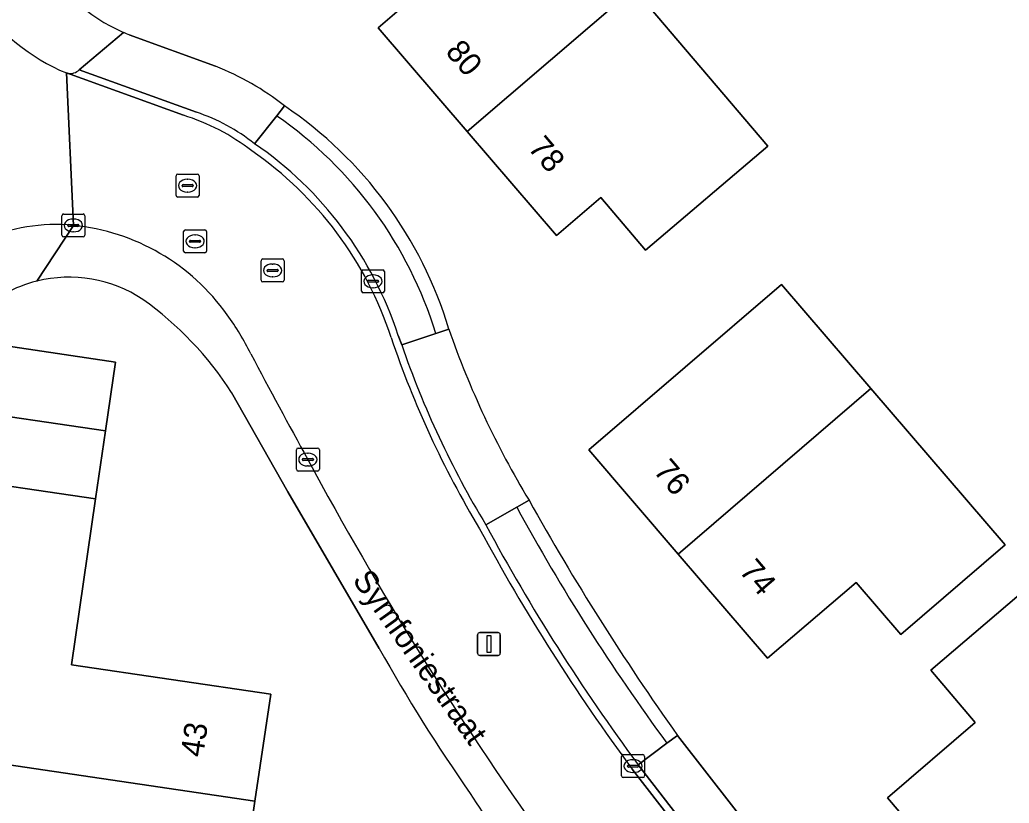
# Model space of a CAD drawing. Extents: x 164148 to 165261, y 382513 to 383432.
# Drawn here: x 164542.81 to 164585.98, y 383274.98 to 383309.16 of the extents above; entities that cross this region are included whole.
import ezdxf

# ---------------------------------------------------------------- set-up
doc = ezdxf.new("R2010")
doc.units = 0
for name, color, linetype in [('IMGEO_Erf', 7, 'Continuous'), ('IMGEO_Kolk', 7, 'Continuous'), ('IMGEO_Lichtmast', 7, 'Continuous'), ('IMGEO_Openbare_ruimte_label', 7, 'Continuous'), ('IMGEO_Pand', 7, 'Continuous'), ('IMGEO_Pand_nummerreeks', 7, 'Continuous'), ('IMGEO_Parkeervlak_open', 7, 'Continuous'), ('IMGEO_Rijbaan_lokaal_open', 7, 'Continuous'), ('IMGEO_Rioolput', 7, 'Continuous'), ('IMGEO_Voetpad_open', 7, 'Continuous')]:
    doc.layers.add(name, color=color, linetype=linetype)

msp = doc.modelspace()

# ---------------------------------------------------------------- linework, layer by layer
at = {"layer": 'IMGEO_Erf'}
for points in [[(164566.222, 383299.749), (164562.332, 383304.282), (164558.441, 383308.814), (164560.383, 383310.481), (164558.414, 383312.774), (164562.969, 383316.671), (164568.685, 383310.059), (164569.447, 383310.707), (164569.603, 383310.523), (164575.452, 383303.652), (164570.113, 383299.108), (164568.162, 383301.401)], [(164575.428, 383281.306), (164571.531, 383285.848), (164567.633, 383290.391), (164576.048, 383297.611), (164579.945, 383293.069), (164585.796, 383286.25), (164581.243, 383282.343), (164579.295, 383284.613)], [(164588.439, 383266.118), (164586.724, 383268.118), (164586.214, 383267.684), (164584.449, 383269.761), (164584.944, 383270.195), (164584.546, 383270.661), (164580.662, 383275.211), (164584.498, 383278.504), (164582.553, 383280.79), (164588.787, 383286.094), (164594.61, 383279.268), (164594.769, 383279.082), (164593.111, 383277.661), (164598.792, 383271.032), (164593.881, 383266.823), (164591.925, 383269.105)]]:
    msp.add_lwpolyline(points, close=True, dxfattribs=at)
for points in [[(164547.58, 383308.512), (164551.344, 383307.132)], [(164540.939, 383296.326), (164540.567, 383295.814), (164540.337, 383295.423), (164540.249, 383295.225), (164546.982, 383294.222), (164546.544, 383291.22), (164546.111, 383288.252), (164545.056, 383281.021), (164553.756, 383279.732), (164553.067, 383275.067), (164552.375, 383270.375), (164543.647, 383271.663), (164543.047, 383267.603), (164542.443, 383263.513), (164550.997, 383262.244), (164559.534, 383260.978), (164560.177, 383265.291), (164566.914, 383264.296), (164565.584, 383255.322), (164564.251, 383246.318), (164583.934, 383243.607)], [(164558.482, 383281.733), (164554.501, 383288.56), (164552.049, 383292.901)], [(164571.503, 383277.936), (164576.415, 383271.617), (164580.653, 383266.29), (164582.585, 383263.961), (164583.944, 383262.272), (164585.284, 383260.567)]]:
    msp.add_lwpolyline(points, dxfattribs=at)
for centre, radius, start, end in [((164550.138, 383315.173), 7.135, 166.9987, 246.8254), ((164550.095, 383315.035), 6.991, 246.698, 248.9111), ((164547.2, 383296.429), 11.477, 51.4118, 68.8368), ((164544.282, 383290.474), 18.01, 16.7439, 55.9762), ((164544.956, 383292.103), 5.829, 103.9701, 133.5672), ((164544.954, 383292.112), 5.819, 56.42, 103.9687), ((164539.532, 383284.826), 14.896, 32.8263, 54.5462), ((164598.416, 383308.4), 39.025, 199.0502, 211.1685), ((164661.715, 383342.047), 110.672, 209.1126, 215.40047), ((164627.145, 383320.437), 78.819, 209.40896, 214.84708), ((164640.067, 383326.157), 92.732, 213.18571, 215.54367)]:
    msp.add_arc(centre, radius, start, end, dxfattribs=at)
at = {"layer": 'IMGEO_Kolk'}
for p, q in [((164544.641, 383299.761), (164544.641, 383300.613)), ((164544.716, 383300.687), (164545.568, 383300.687)), ((164545.642, 383300.613), (164545.642, 383299.761)), ((164544.9, 383300.181), (164544.9, 383300.193)), ((164545.338, 383300.144), (164544.94, 383300.144)), ((164544.943, 383300.23), (164545.341, 383300.23)), ((164545.129, 383300.467), (164545.154, 383300.467)), ((164545.384, 383300.193), (164545.384, 383300.181)), ((164545.152, 383299.907), (164545.127, 383299.907)), ((164545.568, 383299.687), (164544.716, 383299.687)), ((164553.335, 383297.798), (164553.335, 383298.65)), ((164553.41, 383298.724), (164554.262, 383298.724)), ((164553.823, 383298.504), (164553.848, 383298.504)), ((164554.336, 383298.65), (164554.336, 383297.798)), ((164553.594, 383298.218), (164553.594, 383298.23)), ((164554.032, 383298.181), (164553.634, 383298.181)), ((164553.637, 383298.267), (164554.035, 383298.267)), ((164554.078, 383298.23), (164554.078, 383298.218)), ((164557.717, 383297.324), (164557.717, 383298.176)), ((164557.792, 383298.25), (164558.644, 383298.25)), ((164558.205, 383298.03), (164558.23, 383298.03)), ((164558.718, 383298.176), (164558.718, 383297.324)), ((164554.262, 383297.724), (164553.41, 383297.724)), ((164553.846, 383297.944), (164553.821, 383297.944)), ((164557.976, 383297.744), (164557.976, 383297.756)), ((164558.414, 383297.707), (164558.016, 383297.707)), ((164558.019, 383297.793), (164558.417, 383297.793)), ((164558.46, 383297.756), (164558.46, 383297.744)), ((164558.644, 383297.25), (164557.792, 383297.25)), ((164558.228, 383297.47), (164558.203, 383297.47)), ((164554.875, 383289.547), (164554.875, 383290.399)), ((164554.95, 383290.473), (164555.802, 383290.473)), ((164555.363, 383290.253), (164555.388, 383290.253)), ((164555.876, 383290.399), (164555.876, 383289.547)), ((164555.134, 383289.967), (164555.134, 383289.979)), ((164555.572, 383289.93), (164555.174, 383289.93)), ((164555.177, 383290.016), (164555.575, 383290.016)), ((164555.618, 383289.979), (164555.618, 383289.967)), ((164555.802, 383289.473), (164554.95, 383289.473)), ((164555.386, 383289.693), (164555.361, 383289.693)), ((164569.063, 383276.171), (164569.063, 383277.023)), ((164569.138, 383277.097), (164569.99, 383277.097)), ((164569.551, 383276.877), (164569.576, 383276.877)), ((164570.064, 383277.023), (164570.064, 383276.171)), ((164569.322, 383276.591), (164569.322, 383276.603)), ((164569.76, 383276.554), (164569.362, 383276.554)), ((164569.365, 383276.64), (164569.763, 383276.64)), ((164569.806, 383276.603), (164569.806, 383276.591)), ((164569.99, 383276.097), (164569.138, 383276.097)), ((164569.574, 383276.317), (164569.549, 383276.317))]:
    msp.add_line(p, q, dxfattribs=at)
for points in [[(164544.641, 383299.761), (164544.641, 383300.613)], [(164544.716, 383300.687), (164545.568, 383300.687)], [(164545.642, 383300.613), (164545.642, 383299.761)], [(164545.568, 383299.687), (164544.716, 383299.687)], [(164553.335, 383297.798), (164553.335, 383298.65)], [(164553.41, 383298.724), (164554.262, 383298.724)], [(164554.336, 383298.65), (164554.336, 383297.798)], [(164557.717, 383297.324), (164557.717, 383298.176)], [(164557.792, 383298.25), (164558.644, 383298.25)], [(164558.718, 383298.176), (164558.718, 383297.324)], [(164554.262, 383297.724), (164553.41, 383297.724)], [(164558.644, 383297.25), (164557.792, 383297.25)], [(164554.875, 383289.547), (164554.875, 383290.399)], [(164554.95, 383290.473), (164555.802, 383290.473)], [(164555.876, 383290.399), (164555.876, 383289.547)], [(164555.802, 383289.473), (164554.95, 383289.473)], [(164569.063, 383276.171), (164569.063, 383277.023)], [(164569.138, 383277.097), (164569.99, 383277.097)], [(164570.064, 383277.023), (164570.064, 383276.171)], [(164569.99, 383276.097), (164569.138, 383276.097)]]:
    msp.add_lwpolyline(points, dxfattribs=at)
for centre, radius, start, end in [((164544.718, 383300.611), 0.0765, 91.552, 178.448), ((164544.718, 383300.611), 0.0765, 91.552, 178.448), ((164545.566, 383300.611), 0.0765, 1.552, 88.448), ((164545.566, 383300.611), 0.0765, 1.552, 88.448), ((164544.94, 383300.19), 0.0403, 85.8775, 175.7526), ((164544.937, 383300.18), 0.0366, 178.938, 274.7102), ((164545.341, 383300.187), 0.043, 264.8664, 352.4533), ((164545.345, 383300.192), 0.0386, 1.7309, 96.639), ((164544.718, 383299.763), 0.0765, 181.552, 268.448), ((164544.718, 383299.763), 0.0765, 181.552, 268.448), ((164545.566, 383299.763), 0.0765, 271.552, 358.448), ((164545.566, 383299.763), 0.0765, 271.552, 358.448), ((164553.412, 383298.648), 0.0765, 91.552, 178.448), ((164553.412, 383298.648), 0.0765, 91.552, 178.448), ((164554.26, 383298.648), 0.0765, 1.552, 88.448), ((164554.26, 383298.648), 0.0765, 1.552, 88.448), ((164553.634, 383298.227), 0.0403, 85.8775, 175.7526), ((164553.631, 383298.217), 0.0366, 178.938, 274.7102), ((164554.035, 383298.224), 0.043, 264.8664, 352.4533), ((164554.039, 383298.229), 0.0386, 1.7309, 96.639), ((164557.794, 383298.174), 0.0765, 91.552, 178.448), ((164557.794, 383298.174), 0.0765, 91.552, 178.448), ((164558.642, 383298.174), 0.0765, 1.552, 88.448), ((164558.642, 383298.174), 0.0765, 1.552, 88.448), ((164553.412, 383297.8), 0.0765, 181.552, 268.448), ((164553.412, 383297.8), 0.0765, 181.552, 268.448), ((164554.26, 383297.8), 0.0765, 271.552, 358.448), ((164554.26, 383297.8), 0.0765, 271.552, 358.448), ((164558.016, 383297.753), 0.0403, 85.8775, 175.7526), ((164558.013, 383297.743), 0.0366, 178.938, 274.7102), ((164558.417, 383297.75), 0.043, 264.8664, 352.4533), ((164558.421, 383297.755), 0.0386, 1.7309, 96.639), ((164557.794, 383297.326), 0.0765, 181.552, 268.448), ((164557.794, 383297.326), 0.0765, 181.552, 268.448), ((164558.642, 383297.326), 0.0765, 271.552, 358.448), ((164558.642, 383297.326), 0.0765, 271.552, 358.448), ((164554.952, 383290.397), 0.0765, 91.552, 178.448), ((164554.952, 383290.397), 0.0765, 91.552, 178.448), ((164555.8, 383290.397), 0.0765, 1.552, 88.448), ((164555.8, 383290.397), 0.0765, 1.552, 88.448), ((164555.174, 383289.976), 0.0403, 85.8775, 175.7526), ((164555.171, 383289.966), 0.0366, 178.938, 274.7102), ((164555.575, 383289.973), 0.043, 264.8664, 352.4533), ((164555.579, 383289.978), 0.0386, 1.7309, 96.639), ((164554.952, 383289.549), 0.0765, 181.552, 268.448), ((164554.952, 383289.549), 0.0765, 181.552, 268.448), ((164555.8, 383289.549), 0.0765, 271.552, 358.448), ((164555.8, 383289.549), 0.0765, 271.552, 358.448), ((164569.14, 383277.021), 0.0765, 91.552, 178.448), ((164569.14, 383277.021), 0.0765, 91.552, 178.448), ((164569.988, 383277.021), 0.0765, 1.552, 88.448), ((164569.988, 383277.021), 0.0765, 1.552, 88.448), ((164569.362, 383276.6), 0.0403, 85.8775, 175.7526), ((164569.359, 383276.59), 0.0366, 178.938, 274.7102), ((164569.763, 383276.597), 0.043, 264.8664, 352.4533), ((164569.767, 383276.602), 0.0386, 1.7309, 96.639), ((164569.14, 383276.173), 0.0765, 181.552, 268.448), ((164569.14, 383276.173), 0.0765, 181.552, 268.448), ((164569.988, 383276.173), 0.0765, 271.552, 358.448), ((164569.988, 383276.173), 0.0765, 271.552, 358.448)]:
    msp.add_arc(centre, radius, start, end, dxfattribs=at)
for centre, major_axis, ratio, start_param, end_param in [((164545.128, 383300.187), (-0.387, 0.002), 0.722429, 4.712389, 7.853982), ((164545.153, 383300.187), (-0.39, 0.002), 0.717154, 1.570796, 4.712389), ((164553.822, 383298.224), (-0.387, 0.002), 0.722429, 4.712389, 7.853982), ((164553.847, 383298.224), (-0.39, 0.002), 0.717154, 1.570796, 4.712389), ((164558.204, 383297.75), (-0.387, 0.002), 0.722429, 4.712389, 7.853982), ((164558.229, 383297.75), (-0.39, 0.002), 0.717154, 1.570796, 4.712389), ((164555.362, 383289.973), (-0.387, 0.002), 0.722429, 4.712389, 7.853982), ((164555.387, 383289.973), (-0.39, 0.002), 0.717154, 1.570796, 4.712389), ((164569.55, 383276.597), (-0.387, 0.002), 0.722429, 4.712389, 7.853982), ((164569.575, 383276.597), (-0.39, 0.002), 0.717154, 1.570796, 4.712389)]:
    msp.add_ellipse(centre, major_axis=major_axis, ratio=ratio, start_param=start_param, end_param=end_param, dxfattribs=at)
at = {"layer": 'IMGEO_Lichtmast'}
for p, q in [((164562.783, 383281.525), (164562.783, 383282.325)), ((164562.783, 383282.325), (164562.783, 383281.525)), ((164562.883, 383282.425), (164563.673, 383282.425)), ((164563.673, 383282.425), (164562.883, 383282.425)), ((164563.773, 383282.325), (164563.773, 383281.525)), ((164563.773, 383281.525), (164563.773, 383282.325)), ((164563.673, 383281.425), (164562.883, 383281.425)), ((164562.883, 383281.425), (164563.673, 383281.425))]:
    msp.add_line(p, q, dxfattribs=at)
msp.add_lwpolyline([(164563.203, 383282.3), (164563.353, 383282.3), (164563.353, 383281.55), (164563.203, 383281.55), (164563.203, 383282.3)], dxfattribs=at)
for centre, start, end in [((164562.883, 383282.325), 90, 180), ((164562.883, 383282.325), 90, 180), ((164563.673, 383282.325), 0, 90), ((164563.673, 383282.325), 360, 90), ((164562.883, 383281.525), 180, 270), ((164562.883, 383281.525), 180, 270), ((164563.673, 383281.525), 270, 0), ((164563.673, 383281.525), 270, 0)]:
    msp.add_arc(centre, 0.1, start, end, dxfattribs=at)
at = {"layer": 'IMGEO_Pand'}
for points in [[(164569.603, 383310.523), (164569.447, 383310.707), (164568.685, 383310.059), (164562.969, 383316.671), (164558.414, 383312.774), (164560.383, 383310.481), (164558.441, 383308.814), (164562.332, 383304.282)], [(164569.603, 383310.523), (164562.332, 383304.282), (164566.222, 383299.749), (164568.162, 383301.401), (164570.113, 383299.108), (164575.452, 383303.652)], [(164579.945, 383293.069), (164576.048, 383297.611), (164567.633, 383290.391), (164571.531, 383285.848)], [(164539.803, 383292.218), (164546.544, 383291.22), (164546.982, 383294.222), (164540.249, 383295.225)], [(164579.945, 383293.069), (164571.531, 383285.848), (164575.428, 383281.306), (164579.295, 383284.613), (164581.243, 383282.343), (164585.796, 383286.25)], [(164539.362, 383289.25), (164546.111, 383288.252), (164546.544, 383291.22), (164539.803, 383292.218)], [(164537.597, 383277.356), (164553.067, 383275.067), (164553.756, 383279.732), (164545.056, 383281.021), (164546.111, 383288.252), (164539.362, 383289.25)], [(164594.61, 383279.268), (164588.787, 383286.094), (164582.553, 383280.79), (164584.498, 383278.504), (164580.662, 383275.211), (164584.546, 383270.661)], [(164543.047, 383267.603), (164543.647, 383271.663), (164552.375, 383270.375), (164553.067, 383275.067), (164537.597, 383277.356), (164536.299, 383268.602)]]:
    msp.add_lwpolyline(points, close=True, dxfattribs=at)
at = {"layer": 'IMGEO_Parkeervlak_open'}
for points in [[(164554.014, 383304.967), (164553.048, 383303.754)], [(164559.317, 383295.392), (164559.471, 383294.976), (164560.956, 383295.471)], [(164564.487, 383287.893), (164563.142, 383287.12)], [(164569.788, 383276.659), (164571.04, 383277.591)]]:
    msp.add_lwpolyline(points, dxfattribs=at)
for centre, radius, start, end in [((164543.848, 383290.25), 17.887, 16.9716, 55.3654), ((164543.862, 383290.337), 16.26, 18.1136, 55.6043), ((164645.11, 383331.941), 91.871, 208.64996, 216.27011), ((164639.103, 383328.038), 86.281, 208.30968, 216.5469)]:
    msp.add_arc(centre, radius, start, end, dxfattribs=at)
at = {"layer": 'IMGEO_Rijbaan_lokaal_open'}
for points in [[(164544.837, 383306.841), (164549.942, 383304.996)], [(164545.142, 383300.187), (164544.837, 383306.841)], [(164549.942, 383304.996), (164544.837, 383306.841), (164545.142, 383300.187)], [(164550.516, 383305.129), (164545.397, 383306.979), (164545.349, 383306.939)], [(164559.471, 383294.976), (164559.317, 383295.392)], [(164569.53, 383276.467), (164574.452, 383270.101)], [(164574.452, 383270.101), (164569.53, 383276.467)], [(164574.707, 383270.298), (164569.788, 383276.659)]]:
    msp.add_lwpolyline(points, dxfattribs=at)
for centre, radius, start, end in [((164548.388, 383315.25), 9.129, 215.2111, 247.1054), ((164545.003, 383307.359), 0.544, 252.2305, 309.441), ((164547.197, 383296.08), 9.329, 52.0782, 72.8909), ((164547.197, 383296.08), 9.329, 52.0782, 72.8909), ((164547.938, 383297.362), 8.183, 51.3566, 71.6351), ((164543.862, 383290.337), 16.26, 18.1136, 55.6043), ((164543.897, 383290.355), 15.9, 18.0902, 55.3768), ((164543.897, 383290.355), 15.9, 18.0902, 55.3768), ((164544.352, 383292.464), 7.763, 84.1568, 143.902), ((164544.251, 383290.931), 9.298, 35.1831, 84.5028), ((164542.3, 383289.297), 11.837, 26.5256, 36.2085), ((164599.247, 383308.839), 42.455, 198.6077, 211.0297), ((164599.247, 383308.839), 42.455, 198.6077, 211.0297), ((164598.458, 383308.408), 41.236, 199.0106, 211.0815), ((164748.715, 383397.166), 221.066, 207.648, 209.00538), ((164693.124, 383364.005), 156.382, 208.2557, 215.41089), ((164638.908, 383327.907), 86.368, 208.3054, 216.55493), ((164638.908, 383327.907), 86.368, 208.3054, 216.55493), ((164639.103, 383328.038), 86.281, 208.30968, 216.5469)]:
    msp.add_arc(centre, radius, start, end, dxfattribs=at)
at = {"layer": 'IMGEO_Rioolput'}
for p, q in [((164549.626, 383301.5), (164549.626, 383302.352)), ((164549.701, 383302.426), (164550.553, 383302.426)), ((164550.627, 383302.352), (164550.627, 383301.5)), ((164549.885, 383301.92), (164549.885, 383301.932)), ((164550.323, 383301.883), (164549.925, 383301.883)), ((164549.928, 383301.969), (164550.326, 383301.969)), ((164550.114, 383302.206), (164550.139, 383302.206)), ((164550.369, 383301.932), (164550.369, 383301.92)), ((164550.553, 383301.426), (164549.701, 383301.426)), ((164550.137, 383301.646), (164550.112, 383301.646)), ((164549.954, 383299.068), (164549.954, 383299.92)), ((164550.029, 383299.994), (164550.881, 383299.994)), ((164550.442, 383299.774), (164550.467, 383299.774)), ((164550.955, 383299.92), (164550.955, 383299.068)), ((164550.213, 383299.488), (164550.213, 383299.5)), ((164550.651, 383299.451), (164550.253, 383299.451)), ((164550.256, 383299.537), (164550.654, 383299.537)), ((164550.697, 383299.5), (164550.697, 383299.488)), ((164550.881, 383298.994), (164550.029, 383298.994)), ((164550.465, 383299.214), (164550.44, 383299.214))]:
    msp.add_line(p, q, dxfattribs=at)
for points in [[(164549.626, 383301.5), (164549.626, 383302.352)], [(164549.701, 383302.426), (164550.553, 383302.426)], [(164550.627, 383302.352), (164550.627, 383301.5)], [(164550.553, 383301.426), (164549.701, 383301.426)], [(164549.954, 383299.068), (164549.954, 383299.92)], [(164550.029, 383299.994), (164550.881, 383299.994)], [(164550.955, 383299.92), (164550.955, 383299.068)], [(164550.881, 383298.994), (164550.029, 383298.994)]]:
    msp.add_lwpolyline(points, dxfattribs=at)
for centre, radius, start, end in [((164549.703, 383302.35), 0.0765, 91.552, 178.448), ((164549.703, 383302.35), 0.0765, 91.552, 178.448), ((164550.551, 383302.35), 0.0765, 1.552, 88.448), ((164550.551, 383302.35), 0.0765, 1.552, 88.448), ((164549.925, 383301.929), 0.0403, 85.8775, 175.7526), ((164549.922, 383301.919), 0.0366, 178.938, 274.7102), ((164550.326, 383301.926), 0.043, 264.8664, 352.4533), ((164550.33, 383301.931), 0.0386, 1.7309, 96.639), ((164549.703, 383301.502), 0.0765, 181.552, 268.448), ((164549.703, 383301.502), 0.0765, 181.552, 268.448), ((164550.551, 383301.502), 0.0765, 271.552, 358.448), ((164550.551, 383301.502), 0.0765, 271.552, 358.448), ((164550.031, 383299.918), 0.0765, 91.552, 178.448), ((164550.031, 383299.918), 0.0765, 91.552, 178.448), ((164550.879, 383299.918), 0.0765, 1.552, 88.448), ((164550.879, 383299.918), 0.0765, 1.552, 88.448), ((164550.253, 383299.497), 0.0403, 85.8775, 175.7526), ((164550.25, 383299.487), 0.0366, 178.938, 274.7102), ((164550.654, 383299.494), 0.043, 264.8664, 352.4533), ((164550.658, 383299.499), 0.0386, 1.7309, 96.639), ((164550.031, 383299.07), 0.0765, 181.552, 268.448), ((164550.031, 383299.07), 0.0765, 181.552, 268.448), ((164550.879, 383299.07), 0.0765, 271.552, 358.448), ((164550.879, 383299.07), 0.0765, 271.552, 358.448)]:
    msp.add_arc(centre, radius, start, end, dxfattribs=at)
for centre, major_axis, ratio, start_param, end_param in [((164550.113, 383301.926), (-0.387, 0.002), 0.722429, 4.712389, 7.853982), ((164550.138, 383301.926), (-0.39, 0.002), 0.717154, 1.570796, 4.712389), ((164550.441, 383299.494), (-0.387, 0.002), 0.722429, 4.712389, 7.853982), ((164550.466, 383299.494), (-0.39, 0.002), 0.717154, 1.570796, 4.712389)]:
    msp.add_ellipse(centre, major_axis=major_axis, ratio=ratio, start_param=start_param, end_param=end_param, dxfattribs=at)
at = {"layer": 'IMGEO_Voetpad_open'}
for points in [[(164545.349, 383306.939), (164545.397, 383306.979), (164547.33, 383308.614)], [(164547.33, 383308.614), (164545.397, 383306.979), (164550.516, 383305.129)], [(164551.344, 383307.132), (164547.58, 383308.512)], [(164553.048, 383303.754), (164554.014, 383304.967), (164554.359, 383305.4)], [(164554.359, 383305.4), (164554.014, 383304.967)], [(164545.142, 383300.187), (164543.549, 383297.759)], [(164543.549, 383297.759), (164545.142, 383300.187)], [(164561.528, 383295.662), (164560.956, 383295.471), (164559.471, 383294.976)], [(164560.956, 383295.471), (164561.528, 383295.662)], [(164552.049, 383292.901), (164554.501, 383288.56), (164558.482, 383281.733)], [(164563.142, 383287.12), (164564.487, 383287.893), (164565.024, 383288.202)], [(164565.024, 383288.202), (164564.487, 383287.893)], [(164571.04, 383277.591), (164571.503, 383277.936)]]:
    msp.add_lwpolyline(points, dxfattribs=at)
msp.add_lwpolyline([(164571.503, 383277.936), (164571.04, 383277.591), (164569.788, 383276.659), (164574.707, 383270.298), (164575.947, 383271.255), (164576.415, 383271.617)], close=True, dxfattribs=at)
for centre, radius, start, end in [((164550.138, 383315.173), 7.135, 166.9987, 246.8254), ((164548.388, 383315.25), 9.129, 215.2111, 247.1054), ((164550.095, 383315.035), 6.991, 246.698, 248.9111), ((164547.2, 383296.429), 11.477, 51.4118, 68.8368), ((164545.003, 383307.359), 0.544, 252.2305, 309.441), ((164544.282, 383290.474), 18.01, 16.7439, 55.9762), ((164547.938, 383297.362), 8.183, 51.3566, 71.6351), ((164543.848, 383290.25), 17.887, 16.9716, 55.3654), ((164544.352, 383292.464), 7.763, 84.1568, 143.902), ((164544.251, 383290.931), 9.298, 35.1831, 84.5028), ((164544.956, 383292.103), 5.829, 103.9701, 133.5672), ((164544.954, 383292.112), 5.819, 56.42, 103.9687), ((164539.532, 383284.826), 14.896, 32.8263, 54.5462), ((164542.3, 383289.297), 11.837, 26.5256, 36.2085), ((164598.416, 383308.4), 39.025, 199.0502, 211.1685), ((164598.458, 383308.408), 41.236, 199.0106, 211.0815), ((164748.715, 383397.166), 221.066, 207.648, 209.00538), ((164693.124, 383364.005), 156.382, 208.2557, 215.41089), ((164661.715, 383342.047), 110.672, 209.1126, 215.40047), ((164645.11, 383331.941), 91.871, 208.64996, 216.27011), ((164627.145, 383320.437), 78.819, 209.40896, 214.84708), ((164640.067, 383326.157), 92.732, 213.18571, 215.54367)]:
    msp.add_arc(centre, radius, start, end, dxfattribs=at)

# ---------------------------------------------------------------- texts
at = {"layer": 'IMGEO_Openbare_ruimte_label'}
msp.add_text('Symfoniestraat', height=1, rotation=305.3911, dxfattribs=at).set_placement((164557.29, 383284.711))
at = {"layer": 'IMGEO_Pand_nummerreeks'}
for s, rotation, p in [('80', 310.4449, (164561.339, 383307.746)), ('78', 310.4449, (164564.941, 383303.55)), ('76', 310.4334, (164570.416, 383289.455)), ('74', 310.4334, (164574.16, 383285.091)), ('43', 81.6006, (164550.799, 383276.953))]:
    msp.add_text(s, height=1, rotation=rotation, dxfattribs=at).set_placement(p)

doc.saveas('drawing.dxf')
